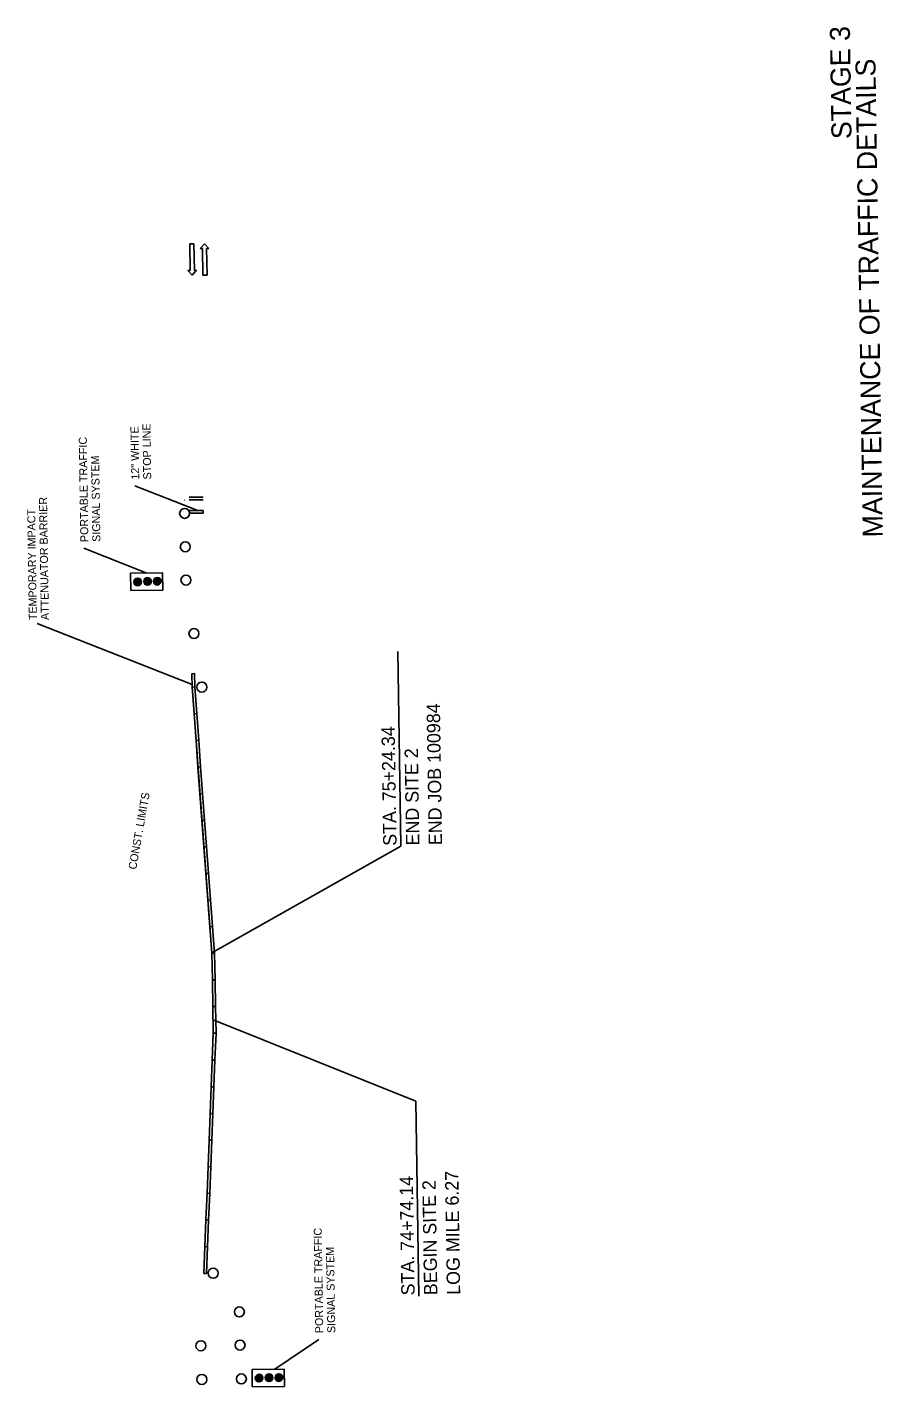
# Model space of a CAD drawing. Extents: x 1770018 to 1773492, y 718230 to 729141.
# Drawn here: x 1770650 to 1771291, y 726618 to 727637 of the extents above; entities that cross this region are included whole.
import ezdxf

# ---------------------------------------------------------------- set-up
doc = ezdxf.new("R2010")
doc.units = 0
for name, color, linetype in [('Default', 7, 'Continuous'), ('R_Border Notes', 7, 'Continuous'), ('R_Dimension', 7, 'Continuous'), ('R_MOT', 7, 'Continuous'), ('R_Striping', 7, 'Continuous'), ('T_Vehicle Path Rt', 7, 'Continuous')]:
    doc.layers.add(name, color=color, linetype=linetype)

msp = doc.modelspace()

# ---------------------------------------------------------------- linework, layer by layer
at = {"layer": 'Default'}
for p, q in [((1770767.5, 727283), (1770767.7, 727283)), ((1770733, 727218.8), (1770729.5, 727222.2)), ((1770732.9, 727218.8), (1770729.5, 727222)), ((1770732.7, 727218.8), (1770729.5, 727221.9)), ((1770732.5, 727218.7), (1770729.5, 727221.7)), ((1770732.4, 727218.7), (1770729.5, 727221.5)), ((1770732.2, 727218.7), (1770729.5, 727221.3)), ((1770732, 727218.8), (1770729.5, 727221.1)), ((1770733.3, 727218.9), (1770729.6, 727222.5)), ((1770733.1, 727218.8), (1770729.6, 727222.3)), ((1770731.8, 727218.8), (1770729.6, 727220.9)), ((1770731.5, 727218.9), (1770729.6, 727220.7)), ((1770733.5, 727219), (1770729.7, 727222.7)), ((1770733.4, 727218.9), (1770729.7, 727222.6)), ((1770733.8, 727219.1), (1770729.8, 727223)), ((1770733.7, 727219), (1770729.8, 727222.8)), ((1770731.2, 727219), (1770729.8, 727220.4)), ((1770734, 727219.2), (1770729.9, 727223.2)), ((1770733.9, 727219.2), (1770729.9, 727223.1)), ((1770734.1, 727219.3), (1770730, 727223.3)), ((1770730.8, 727219.2), (1770730, 727220)), ((1770734.2, 727219.4), (1770730.1, 727223.4)), ((1770734.3, 727219.5), (1770730.2, 727223.5)), ((1770734.5, 727219.7), (1770730.3, 727223.7)), ((1770734.4, 727219.6), (1770730.3, 727223.6)), ((1770734.6, 727219.8), (1770730.4, 727223.7)), ((1770734.6, 727219.8), (1770730.5, 727223.8)), ((1770734.7, 727220), (1770730.6, 727223.9)), ((1770734.8, 727220.1), (1770730.7, 727224)), ((1770734.8, 727220.2), (1770730.8, 727224.1)), ((1770734.9, 727220.3), (1770730.9, 727224.1)), ((1770735, 727220.4), (1770731.1, 727224.2)), ((1770735, 727220.5), (1770731.2, 727224.2)), ((1770735.1, 727220.6), (1770731.3, 727224.3)), ((1770735.1, 727220.8), (1770731.4, 727224.3)), ((1770735.1, 727220.9), (1770731.6, 727224.4)), ((1770735.2, 727221.1), (1770731.7, 727224.4)), ((1770735.2, 727221.2), (1770731.9, 727224.4)), ((1770735.2, 727221.4), (1770732, 727224.5)), ((1770735.2, 727221.5), (1770732.2, 727224.5)), ((1770735.2, 727221.7), (1770732.4, 727224.5)), ((1770735.2, 727221.9), (1770732.5, 727224.5)), ((1770735.2, 727222.1), (1770732.7, 727224.5)), ((1770735.2, 727222.3), (1770733, 727224.4)), ((1770735.1, 727222.5), (1770733.2, 727224.4)), ((1770735, 727222.8), (1770733.5, 727224.3)), ((1770734.7, 727223.2), (1770733.9, 727224)), ((1770740.5, 727219.2), (1770737, 727222.6)), ((1770740.3, 727219.2), (1770737, 727222.4)), ((1770740.2, 727219.1), (1770737, 727222.2)), ((1770740, 727219.1), (1770737, 727222.1)), ((1770739.8, 727219.1), (1770737, 727221.9)), ((1770739.7, 727219.1), (1770737, 727221.7)), ((1770739.5, 727219.1), (1770737, 727221.5)), ((1770739.2, 727219.2), (1770737, 727221.3)), ((1770740.9, 727219.3), (1770737.1, 727223)), ((1770740.8, 727219.3), (1770737.1, 727222.8)), ((1770740.6, 727219.2), (1770737.1, 727222.7)), ((1770739, 727219.2), (1770737.1, 727221.1)), ((1770741.1, 727219.4), (1770737.2, 727223.2)), ((1770741, 727219.4), (1770737.2, 727223.1)), ((1770738.7, 727219.4), (1770737.2, 727220.8)), ((1770741.3, 727219.5), (1770737.3, 727223.3)), ((1770741.5, 727219.6), (1770737.4, 727223.6)), ((1770741.4, 727219.6), (1770737.4, 727223.4)), ((1770741.6, 727219.7), (1770737.5, 727223.7)), ((1770738.3, 727219.6), (1770737.5, 727220.4)), ((1770741.7, 727219.8), (1770737.6, 727223.8)), ((1770741.9, 727219.9), (1770737.7, 727223.9)), ((1770741.8, 727219.9), (1770737.7, 727223.9)), ((1770741.9, 727220), (1770737.8, 727224)), ((1770742, 727220.1), (1770737.9, 727224.1)), ((1770742.1, 727220.2), (1770738, 727224.2)), ((1770742.2, 727220.3), (1770738.1, 727224.3)), ((1770742.3, 727220.4), (1770738.2, 727224.4)), ((1770742.3, 727220.5), (1770738.3, 727224.4)), ((1770742.4, 727220.7), (1770738.4, 727224.5)), ((1770742.4, 727220.8), (1770738.5, 727224.6)), ((1770742.5, 727220.9), (1770738.7, 727224.6)), ((1770742.5, 727221), (1770738.8, 727224.7)), ((1770742.6, 727221.2), (1770738.9, 727224.7)), ((1770742.6, 727221.3), (1770739.1, 727224.8)), ((1770742.7, 727221.4), (1770739.2, 727224.8)), ((1770742.7, 727221.6), (1770739.3, 727224.8)), ((1770742.7, 727221.7), (1770739.5, 727224.8)), ((1770742.7, 727221.9), (1770739.7, 727224.9)), ((1770742.7, 727222.1), (1770739.8, 727224.9)), ((1770742.7, 727222.3), (1770740, 727224.9)), ((1770742.7, 727222.5), (1770740.2, 727224.8)), ((1770742.6, 727222.7), (1770740.4, 727224.8)), ((1770742.6, 727222.9), (1770740.7, 727224.7)), ((1770742.4, 727223.2), (1770741, 727224.6)), ((1770742.2, 727223.6), (1770741.4, 727224.4)), ((1770747.4, 727219.2), (1770744.2, 727222.3)), ((1770747.2, 727219.2), (1770744.2, 727222.1)), ((1770747, 727219.2), (1770744.2, 727221.9)), ((1770748, 727219.4), (1770744.3, 727222.9)), ((1770747.8, 727219.3), (1770744.3, 727222.7)), ((1770747.7, 727219.3), (1770744.3, 727222.6)), ((1770747.5, 727219.3), (1770744.3, 727222.4)), ((1770746.8, 727219.2), (1770744.3, 727221.7)), ((1770746.6, 727219.3), (1770744.3, 727221.5)), ((1770748.2, 727219.5), (1770744.4, 727223.1)), ((1770748.1, 727219.4), (1770744.4, 727223)), ((1770746.4, 727219.3), (1770744.4, 727221.3)), ((1770746.1, 727219.4), (1770744.4, 727221)), ((1770748.5, 727219.6), (1770744.5, 727223.4)), ((1770748.3, 727219.5), (1770744.5, 727223.3)), ((1770748.6, 727219.6), (1770744.6, 727223.5)), ((1770745.8, 727219.6), (1770744.6, 727220.7)), ((1770748.8, 727219.8), (1770744.7, 727223.7)), ((1770748.7, 727219.7), (1770744.7, 727223.6)), ((1770748.9, 727219.8), (1770744.8, 727223.8)), ((1770749, 727219.9), (1770744.9, 727223.9)), ((1770749.2, 727220.1), (1770745, 727224.1)), ((1770749.1, 727220), (1770745, 727224)), ((1770749.3, 727220.2), (1770745.1, 727224.2)), ((1770749.3, 727220.3), (1770745.2, 727224.3)), ((1770749.4, 727220.4), (1770745.3, 727224.4)), ((1770749.5, 727220.5), (1770745.4, 727224.4)), ((1770749.6, 727220.6), (1770745.5, 727224.5)), ((1770749.6, 727220.7), (1770745.6, 727224.6)), ((1770749.7, 727220.8), (1770745.7, 727224.6)), ((1770749.7, 727220.9), (1770745.9, 727224.7)), ((1770749.8, 727221.2), (1770746.1, 727224.8)), ((1770749.9, 727221.3), (1770746.2, 727224.8)), ((1770749.9, 727221.5), (1770746.4, 727224.9)), ((1770749.9, 727221.6), (1770746.5, 727224.9)), ((1770750, 727221.8), (1770746.7, 727224.9)), ((1770750, 727221.9), (1770746.8, 727225)), ((1770750, 727222.1), (1770747, 727225)), ((1770750, 727222.3), (1770747.2, 727225)), ((1770750, 727222.5), (1770747.4, 727225)), ((1770749.9, 727222.7), (1770747.6, 727224.9)), ((1770749.9, 727222.9), (1770747.8, 727224.9)), ((1770749.8, 727223.2), (1770748.1, 727224.8)), ((1770749.6, 727223.5), (1770748.4, 727224.7)), ((1770749.2, 727224), (1770749, 727224.3)), ((1770929.6, 727023.5), (1770927.3, 727169.4)), ((1770788, 726943.7), (1770929.6, 727023.5)), ((1770788.9, 726893.5), (1770940.9, 726832.4)), ((1770943.1, 726686.4), (1770940.9, 726832.4)), ((1770824.1, 726622.1), (1770820.6, 726625.4)), ((1770823.9, 726622), (1770820.6, 726625.3)), ((1770823.8, 726622), (1770820.6, 726625.1)), ((1770823.6, 726622), (1770820.6, 726624.9)), ((1770823.4, 726622), (1770820.6, 726624.8)), ((1770823.3, 726622), (1770820.6, 726624.6)), ((1770823.1, 726622), (1770820.6, 726624.4)), ((1770824.5, 726622.2), (1770820.7, 726625.8)), ((1770824.4, 726622.1), (1770820.7, 726625.7)), ((1770824.2, 726622.1), (1770820.7, 726625.6)), ((1770824.7, 726622.3), (1770820.8, 726626.1)), ((1770824.6, 726622.2), (1770820.8, 726626)), ((1770824.9, 726622.4), (1770820.9, 726626.2)), ((1770825.1, 726622.5), (1770821, 726626.4)), ((1770825, 726622.4), (1770821, 726626.3)), ((1770825.2, 726622.6), (1770821.1, 726626.5)), ((1770825.3, 726622.6), (1770821.2, 726626.6)), ((1770825.5, 726622.8), (1770821.3, 726626.8)), ((1770825.4, 726622.7), (1770821.3, 726626.7)), ((1770825.6, 726622.9), (1770821.4, 726626.9)), ((1770825.6, 726623), (1770821.5, 726627)), ((1770825.7, 726623.1), (1770821.6, 726627.1)), ((1770825.8, 726623.2), (1770821.7, 726627.2)), ((1770825.9, 726623.3), (1770821.8, 726627.2)), ((1770825.9, 726623.4), (1770821.9, 726627.3)), ((1770826, 726623.5), (1770822, 726627.4)), ((1770826, 726623.6), (1770822.1, 726627.4)), ((1770826.1, 726623.8), (1770822.3, 726627.5)), ((1770826.2, 726623.9), (1770822.4, 726627.5)), ((1770826.2, 726624), (1770822.5, 726627.6)), ((1770826.2, 726624.2), (1770822.7, 726627.6)), ((1770826.3, 726624.3), (1770822.8, 726627.7)), ((1770826.3, 726624.5), (1770823, 726627.7)), ((1770826.3, 726624.6), (1770823.1, 726627.7)), ((1770826.3, 726624.8), (1770823.3, 726627.7)), ((1770826.3, 726624.9), (1770823.4, 726627.7)), ((1770826.3, 726625.1), (1770823.6, 726627.7)), ((1770826.3, 726625.3), (1770823.8, 726627.7)), ((1770826.2, 726625.5), (1770824, 726627.7)), ((1770826.2, 726625.8), (1770824.3, 726627.6)), ((1770826, 726626.1), (1770824.6, 726627.5)), ((1770825.8, 726626.5), (1770825, 726627.3)), ((1770831.7, 726622.5), (1770828.1, 726625.9)), ((1770831.6, 726622.4), (1770828.1, 726625.8)), ((1770831.4, 726622.4), (1770828.1, 726625.6)), ((1770831.3, 726622.4), (1770828.1, 726625.5)), ((1770831.1, 726622.4), (1770828.1, 726625.3)), ((1770830.9, 726622.4), (1770828.1, 726625.2)), ((1770830.7, 726622.4), (1770828.1, 726625)), ((1770830.5, 726622.4), (1770828.1, 726624.8)), ((1770830.3, 726622.4), (1770828.1, 726624.5)), ((1770832, 726622.6), (1770828.2, 726626.2)), ((1770831.8, 726622.5), (1770828.2, 726626.1)), ((1770832.2, 726622.7), (1770828.3, 726626.5)), ((1770832.1, 726622.6), (1770828.3, 726626.3)), ((1770832.5, 726622.8), (1770828.4, 726626.7)), ((1770832.3, 726622.7), (1770828.4, 726626.6)), ((1770832.6, 726622.9), (1770828.5, 726626.8)), ((1770832.7, 726622.9), (1770828.6, 726626.9)), ((1770832.9, 726623.1), (1770828.7, 726627.1)), ((1770832.8, 726623), (1770828.7, 726627)), ((1770832.9, 726623.2), (1770828.8, 726627.2)), ((1770833, 726623.3), (1770828.9, 726627.3)), ((1770833.1, 726623.4), (1770829, 726627.4)), ((1770833.2, 726623.5), (1770829.1, 726627.5)), ((1770833.3, 726623.6), (1770829.2, 726627.5)), ((1770833.3, 726623.7), (1770829.3, 726627.6)), ((1770833.4, 726623.8), (1770829.4, 726627.7)), ((1770833.5, 726623.9), (1770829.5, 726627.7)), ((1770833.5, 726624), (1770829.6, 726627.8)), ((1770833.6, 726624.1), (1770829.7, 726627.9)), ((1770833.6, 726624.3), (1770829.9, 726627.9)), ((1770833.7, 726624.4), (1770830, 726628)), ((1770833.7, 726624.5), (1770830.1, 726628)), ((1770833.7, 726624.7), (1770830.3, 726628)), ((1770833.8, 726624.8), (1770830.4, 726628.1)), ((1770833.8, 726625), (1770830.6, 726628.1)), ((1770833.8, 726625.2), (1770830.8, 726628.1)), ((1770833.8, 726625.3), (1770830.9, 726628.1)), ((1770833.8, 726625.5), (1770831.1, 726628.1)), ((1770833.8, 726625.7), (1770831.3, 726628.1)), ((1770833.7, 726625.9), (1770831.5, 726628)), ((1770833.6, 726626.2), (1770831.8, 726628)), ((1770833.5, 726626.5), (1770832.1, 726627.9)), ((1770833.3, 726626.8), (1770832.5, 726627.7)), ((1770838.6, 726622.5), (1770835.3, 726625.7)), ((1770838.4, 726622.5), (1770835.3, 726625.5)), ((1770838.3, 726622.5), (1770835.3, 726625.3)), ((1770838.1, 726622.5), (1770835.3, 726625.2)), ((1770837.9, 726622.5), (1770835.3, 726625)), ((1770839, 726622.6), (1770835.4, 726626.1)), ((1770838.9, 726622.6), (1770835.4, 726626)), ((1770838.8, 726622.5), (1770835.4, 726625.8)), ((1770837.7, 726622.5), (1770835.4, 726624.8)), ((1770837.5, 726622.6), (1770835.4, 726624.5)), ((1770839.3, 726622.7), (1770835.5, 726626.4)), ((1770839.2, 726622.6), (1770835.5, 726626.2)), ((1770839.5, 726622.8), (1770835.6, 726626.6)), ((1770839.4, 726622.8), (1770835.6, 726626.5)), ((1770839.8, 726622.9), (1770835.7, 726626.8)), ((1770839.7, 726622.9), (1770835.7, 726626.7)), ((1770839.9, 726623), (1770835.8, 726627)), ((1770840, 726623.1), (1770835.9, 726627.1)), ((1770840.2, 726623.3), (1770836, 726627.3)), ((1770840.1, 726623.2), (1770836, 726627.2)), ((1770840.3, 726623.3), (1770836.1, 726627.3)), ((1770840.3, 726623.4), (1770836.2, 726627.4)), ((1770840.4, 726623.5), (1770836.3, 726627.5)), ((1770840.5, 726623.6), (1770836.4, 726627.6)), ((1770840.6, 726623.7), (1770836.5, 726627.7)), ((1770840.6, 726623.8), (1770836.6, 726627.7)), ((1770840.7, 726624), (1770836.7, 726627.8)), ((1770840.8, 726624.1), (1770836.8, 726627.9)), ((1770840.8, 726624.2), (1770837, 726627.9)), ((1770840.9, 726624.4), (1770837.2, 726628)), ((1770841, 726624.6), (1770837.3, 726628.1)), ((1770841, 726624.7), (1770837.5, 726628.1)), ((1770841, 726624.9), (1770837.6, 726628.2)), ((1770841.1, 726625), (1770837.8, 726628.2)), ((1770841.1, 726625.2), (1770837.9, 726628.2)), ((1770841.1, 726625.3), (1770838.1, 726628.2)), ((1770841.1, 726625.5), (1770838.3, 726628.2)), ((1770841, 726625.7), (1770838.5, 726628.2)), ((1770841, 726625.9), (1770838.7, 726628.2)), ((1770841, 726626.1), (1770838.9, 726628.1)), ((1770840.9, 726626.4), (1770839.2, 726628.1)), ((1770840.7, 726626.7), (1770839.5, 726627.9)), ((1770840.3, 726627.3), (1770840.1, 726627.5)), ((1770822.8, 726622), (1770820.7, 726624.2)), ((1770822.6, 726622.1), (1770820.7, 726623.9)), ((1770822.3, 726622.2), (1770820.8, 726623.6)), ((1770821.9, 726622.4), (1770821.1, 726623.3)), ((1770830.1, 726622.5), (1770828.2, 726624.3)), ((1770829.8, 726622.6), (1770828.3, 726624)), ((1770829.4, 726622.8), (1770828.5, 726623.6)), ((1770837.2, 726622.7), (1770835.5, 726624.3)), ((1770836.9, 726622.8), (1770835.7, 726623.9))]:
    msp.add_line(p, q, dxfattribs=at)
for points in [[(1770727.2, 727215.1), (1770727, 727228.1), (1770751, 727228.5), (1770751.2, 727215.5)], [(1770818.3, 726618.4), (1770818.1, 726631.3), (1770842.1, 726631.7), (1770842.3, 726618.7)]]:
    msp.add_lwpolyline(points, close=True, dxfattribs=at)
for centre in [(1770732.4, 727221.6), (1770739.8, 727222), (1770747.1, 727222.1), (1770823.4, 726624.9), (1770830.9, 726625.2), (1770838.2, 726625.3)]:
    msp.add_circle(centre, 2.87, dxfattribs=at)
at = {"layer": 'R_Border Notes'}
for p, q in [((1770774.6, 727475.1), (1770771.4, 727475.1)), ((1770771.4, 727475.1), (1770771.7, 727455.1)), ((1770774.6, 727475.1), (1770774.9, 727455.1)), ((1770779.3, 727471.5), (1770782.5, 727475.1)), ((1770779.3, 727471.5), (1770780.9, 727471.5)), ((1770781.2, 727451.6), (1770780.9, 727471.5)), ((1770782.5, 727475.1), (1770785.7, 727471.6)), ((1770784.4, 727451.6), (1770784.1, 727471.6)), ((1770785.7, 727471.6), (1770784.1, 727471.6)), ((1770773.3, 727451.6), (1770770.1, 727455.1)), ((1770770.1, 727455.1), (1770771.7, 727455.1)), ((1770776.5, 727455.2), (1770773.3, 727451.6)), ((1770776.5, 727455.2), (1770774.9, 727455.1)), ((1770781.2, 727451.6), (1770784.4, 727451.6))]:
    msp.add_line(p, q, dxfattribs=at)
at = {"layer": 'R_Dimension'}
for p, q in [((1770777.4, 727275.2), (1770730.2, 727293.7)), ((1770739.3, 727228.3), (1770692.1, 727246.9)), ((1770773.2, 727144.7), (1770657, 727190.4)), ((1770835.3, 726631.6), (1770868.1, 726653.9))]:
    msp.add_line(p, q, dxfattribs=at)
at = {"layer": 'R_MOT'}
for centre in [(1770767.6, 727273), (1770768.1, 727248), (1770768.6, 727223), (1770774.6, 727182.9), (1770780.5, 727142.8), (1770789, 726703.5), (1770808.6, 726674.5), (1770779.8, 726649.1), (1770809.1, 726649.6), (1770780.5, 726623.9), (1770810.1, 726624.3)]:
    msp.add_circle(centre, 3.75, dxfattribs=at)
at = {"layer": 'R_Striping'}
for p, q in [((1770771.1, 727285.1), (1770781.5, 727285.2)), ((1770771.1, 727283.1), (1770781.5, 727283.2)), ((1770781.6, 727275.2), (1770771.2, 727275.1)), ((1770771.2, 727275.1), (1770771.3, 727274)), ((1770771.4, 727273.1), (1770781.6, 727273.2)), ((1770781.6, 727273.2), (1770781.6, 727275.2))]:
    msp.add_line(p, q, dxfattribs=at)
msp.add_arc((1770767.6, 727273), 3.75, 1.2281, 15.2868, dxfattribs=at)
at = {"layer": 'T_Vehicle Path Rt'}
msp.add_line((1770773.4, 727139.8), (1770788, 726943.3), dxfattribs=at)
for points in [[(1770773.2, 727142.8), (1770773.1, 727152.8), (1770775.1, 727152.9), (1770775.2, 727142.9)], [(1770774.7, 727122.8), (1770773.2, 727142.7), (1770775.2, 727142.9), (1770776.7, 727122.9)], [(1770776.2, 727102.8), (1770774.7, 727122.8), (1770776.7, 727122.9), (1770778.2, 727103)], [(1770777.6, 727082.9), (1770776.2, 727102.8), (1770778.2, 727103), (1770779.6, 727083)], [(1770779.1, 727062.9), (1770777.6, 727082.9), (1770779.6, 727083), (1770781.1, 727063.1)], [(1770780.6, 727043), (1770779.1, 727062.9), (1770781.1, 727063.1), (1770782.6, 727043.1)], [(1770782.1, 727023.1), (1770780.6, 727043), (1770782.6, 727043.1), (1770784.1, 727023.2)], [(1770783.6, 727003.1), (1770782.1, 727023.1), (1770784.1, 727023.2), (1770785.6, 727003.3)], [(1770785.1, 726983.2), (1770783.6, 727003.1), (1770785.6, 727003.3), (1770787, 726983.3)], [(1770786.5, 726963.2), (1770785.1, 726983.2), (1770787, 726983.3), (1770788.5, 726963.4)], [(1770788, 726943.3), (1770786.5, 726963.2), (1770788.5, 726963.4), (1770790, 726943.4)], [(1770788.4, 726923.3), (1770788, 726943.3), (1770790, 726943.3), (1770790.4, 726923.3)], [(1770788.7, 726903.3), (1770788.4, 726923.3), (1770790.4, 726923.3), (1770790.7, 726903.3)], [(1770789.1, 726883.3), (1770788.7, 726903.3), (1770790.7, 726903.3), (1770791.1, 726883.3)], [(1770788.3, 726863.3), (1770789.1, 726883.3), (1770791.1, 726883.2), (1770790.3, 726863.2)], [(1770787.5, 726843.3), (1770788.3, 726863.3), (1770790.3, 726863.2), (1770789.5, 726843.2)], [(1770786.8, 726823.3), (1770787.5, 726843.3), (1770789.5, 726843.2), (1770788.8, 726823.3)], [(1770786, 726803.3), (1770786.8, 726823.3), (1770788.8, 726823.3), (1770788, 726803.3)], [(1770785.2, 726783.4), (1770786, 726803.3), (1770788, 726803.3), (1770787.2, 726783.3)], [(1770784.4, 726763.4), (1770785.2, 726783.4), (1770787.2, 726783.3), (1770786.4, 726763.3)], [(1770783.6, 726743.4), (1770784.4, 726763.4), (1770786.4, 726763.3), (1770785.6, 726743.3)], [(1770782.8, 726723.4), (1770783.6, 726743.4), (1770785.6, 726743.3), (1770784.8, 726723.3)], [(1770782.1, 726703.4), (1770782.8, 726723.4), (1770784.8, 726723.3), (1770784.1, 726703.3)]]:
    msp.add_lwpolyline(points, close=True, dxfattribs=at)

# ---------------------------------------------------------------- texts
at = {"layer": 'Default'}
for s, height, p in [('STAGE 3', 15, (1771267.3, 727553.6)), ('MAINTENANCE OF TRAFFIC DETAILS', 15, (1771290.7, 727255.1)), ('END JOB 100984', 10, (1770960.5, 727024.4)), ('STA. 75+24.34', 10, (1770926.4, 727023.9)), ('END SITE 2', 10, (1770943.5, 727024.2)), ('LOG MILE 6.27', 10, (1770974.1, 726687.4)), ('STA. 74+74.14', 10, (1770940, 726686.9)), ('BEGIN SITE 2', 10, (1770957, 726687.1))]:
    msp.add_text(s, height=height, rotation=90.8827, dxfattribs=at).set_placement(p)
at = {"layer": 'R_Dimension'}
for s, rotation, p in [('12" WHITE', 90.8827, (1770733.6, 727298.4)), ('STOP LINE', 90.8827, (1770742.6, 727298.5)), ('PORTABLE TRAFFIC', 90.8827, (1770695.5, 727251.5)), ('SIGNAL SYSTEM', 90.8827, (1770704.5, 727251.7)), ('ATTENUATOR BARRIER', 90.8827, (1770665.9, 727193.1)), ('TEMPORARY IMPACT', 90.8827, (1770656.9, 727193)), ('CONST. LIMITS', 79.9863, (1770731.3, 727005.7)), ('PORTABLE TRAFFIC', 90.8827, (1770871.5, 726658.6)), ('SIGNAL SYSTEM', 90.8827, (1770880.5, 726658.7))]:
    msp.add_text(s, height=6, rotation=rotation, dxfattribs=at).set_placement(p)

doc.saveas('drawing.dxf')
